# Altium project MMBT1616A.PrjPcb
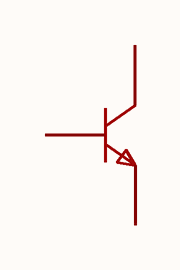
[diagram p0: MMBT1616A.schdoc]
1 sheet, 1 parts. Net scope: global (net labels, ports and power ports of the same name join across sheets).

## Sheet MMBT1616A.schdoc
size 127 x 101 mm

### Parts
Q?  mmbt1616a(range:200-400)  [SOT-23-3_L2.9-W1.3-P1.90-LS2.4-BR]  (value not drawn)

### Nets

Not connected (* = marked no-connect by the designer): Q? 1(B) 2(E) 3(C)

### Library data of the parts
Q? = mmbt1616a(range:200-400): 晶体管类型:NPN;集电极电流(Ic):1A;集射极击穿电压(Vceo):60V;耗散功率(Pd):350mW;直流电流增益(hFE):200;; Manufacturer: CJ(江苏长电/长晶); AddInBom: yes; ModelId: c62791f0466c4ae2a892c056b845b0ca; ModelName: SOT-23-3P_L2.9-W1.3-H1.0-LS2.4-P0.95; ModelTransform: 98.425,114.173,0,180,0,0,0.0005,-0.0005,0; type: NPN; Current - Collector(Ic): 1A; Collector - Emitter Voltage VCEO: 60V; Pd - Power Dissipation: 350mW; DC Current Gain: 200; Transition frequency(fT): 100MHz; Current - Collector Cutoff: 100nA; Vce Saturation(VCE(sat)): 300mV; Emitter-Base Voltage(Vebo): 6V; Number: 1个NPN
